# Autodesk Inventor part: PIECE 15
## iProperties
Created: 2004-11
Part Number: PIECE 15
Document SubType Name: Modeling
Designer: Bruno
Manufacturer: Standard
Standards Organization: Custom
Author: Bruno
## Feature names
1. Base1
